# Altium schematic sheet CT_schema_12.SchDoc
size 386 x 278 mm
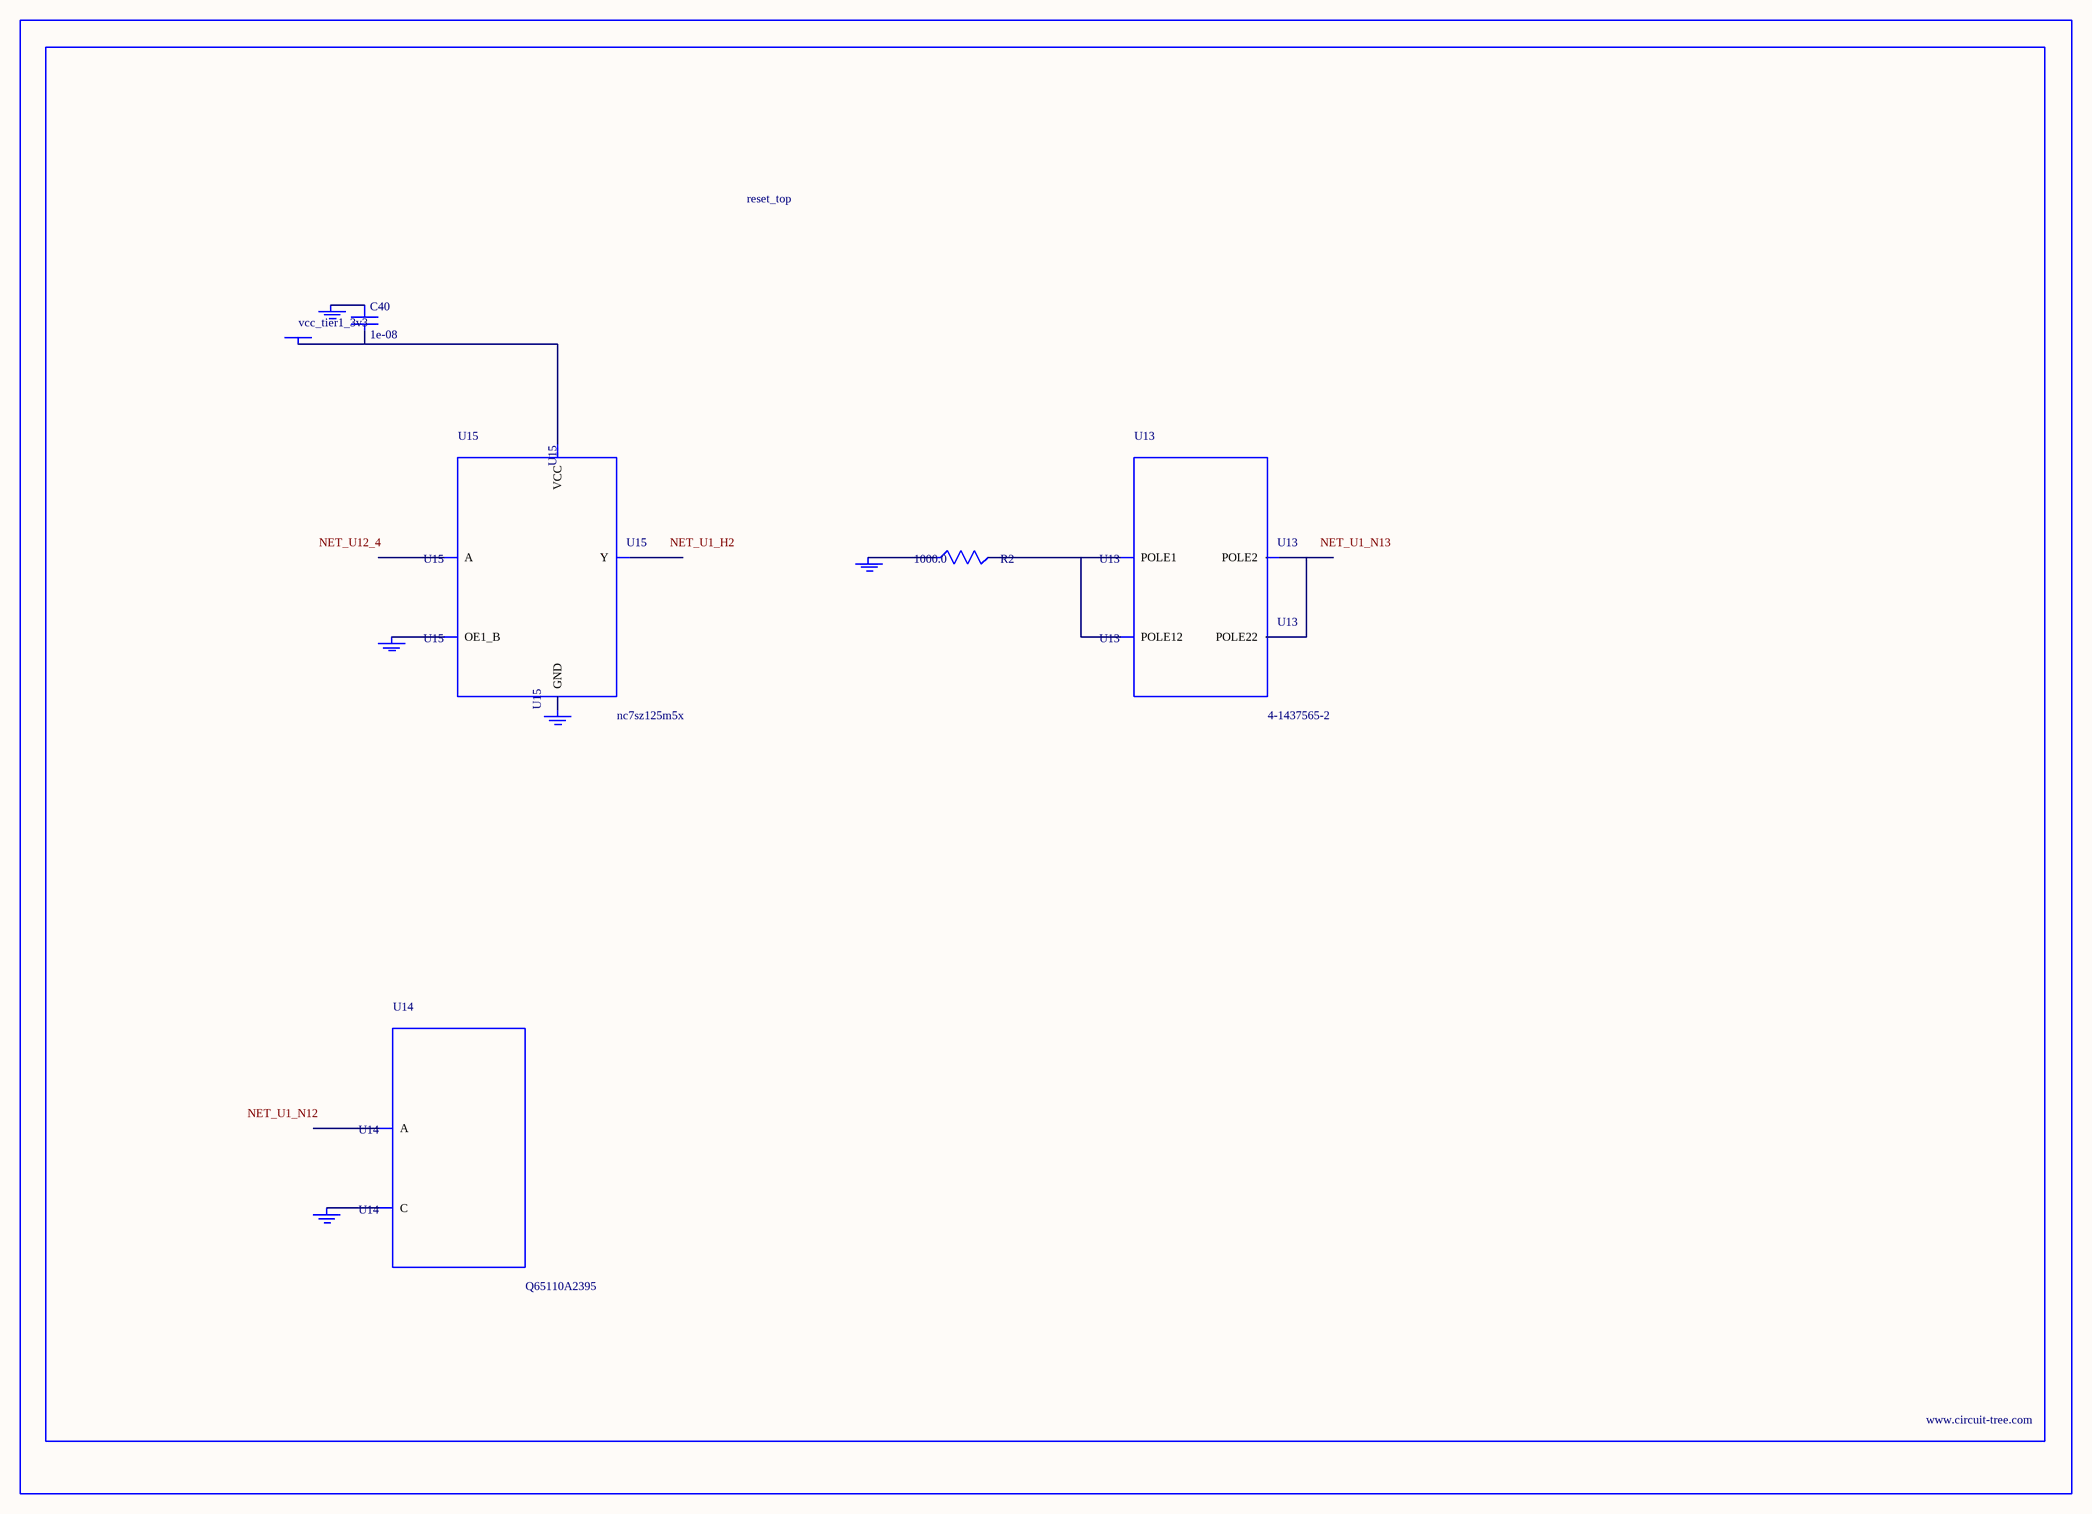
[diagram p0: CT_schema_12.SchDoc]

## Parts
BORDER11  (no value)
C40  1e-08  [C0402]
GND_INSTANCE_11_0  (no value)
GND_INSTANCE_11_1  (no value)
GND_INSTANCE_11_2  (no value)
GND_INSTANCE_11_3  (no value)
GND_INSTANCE_11_4  (no value)
POWER_INSTANCE_11_0  vcc_tier1_3v3
R2  1000.0  [R0603]
U13  4-1437565-2  [SW_4-1437565-2]
U14  Q65110A2395  [LGM67K-G1J2-24-Z]
U15  nc7sz125m5x  [NC7SZ125M5X]

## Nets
NetC40_1: C40.1 GND_INSTANCE_11_2.0(GND)
NetC40_2: C40.2 POWER_INSTANCE_11_0.0(PWR) U15.5(VCC)
NetGND_INSTANCE_11_0_0: GND_INSTANCE_11_0.0(GND) R2.1
NetGND_INSTANCE_11_1_0: GND_INSTANCE_11_1.0(GND) U14.C
NetGND_INSTANCE_11_3_0: GND_INSTANCE_11_3.0(GND) U15.1(OE1_B)
NetGND_INSTANCE_11_4_0: GND_INSTANCE_11_4.0(GND) U15.3(GND)
NetR2_2: R2.2 U13.1(POLE1) U13.2(POLE12)
NetU13_3: U13.3(POLE2) U13.4(POLE22)

Not connected (* = marked no-connect by the designer): U14 A; U15 2(A) 4(Y)

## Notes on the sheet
- Labels drawn without touching a wire or pin: NET_U1_H2, NET_U1_N12, NET_U1_N13, NET_U12_4

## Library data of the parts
BORDER11 = BORDER_PAGE11
C40 = C0402C103K3RAC
GND_INSTANCE_11_0-GND_INSTANCE_11_4 = GND
POWER_INSTANCE_11_0 = PWR
R2 = RC0603JR-071KL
